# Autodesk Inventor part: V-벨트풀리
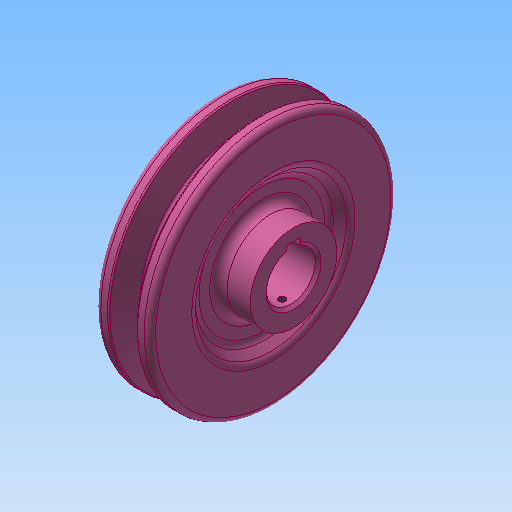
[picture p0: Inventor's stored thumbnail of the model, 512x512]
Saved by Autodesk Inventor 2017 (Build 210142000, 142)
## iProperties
Company: 한국ATC센터
Created: 2015-12
Part Number: V-벨트풀리
Document SubType Name: Modeling
Designer: mdu
Density: 7.25 g/cm^3
Mass: 596.066 g
Surface Area: 214.402 cm^2
Volume: 82.216 cm^3
Material: 주철
Appearance: 분홍색
Author: mdu
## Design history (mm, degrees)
sketch "스케치1"
  geometry: L1 (-13, 0)-(13, 0); L2 (-13, 0)-(-13, 15); L3 (-13, 15)-(-9, 15); L4 (-9, 15)-(-9, 23); L5 (-9, 23)-(-13, 27); L6 (-13, 27)-(-13, 42.7); L7 (-13, 42.7)-(-8.325, 42.7); L8 (-8.325, 42.7)-(-5.574, 33.7); L9 (-5.574, 33.7)-(-1.426, 33.7); L10 (-1.426, 33.7)-(1.325, 42.7); L11 (1.325, 42.7)-(6, 42.7); L12 (6, 42.7)-(6, 27); L13 (6, 27)-(2, 23); L14 (2, 23)-(2, 15); L15 (2, 15)-(13, 15); L16 (13, 15)-(13, 0); L17 (-7.5, 40)-(0.5, 40); 2 further points
  constraints: 34 end point, 6 parallel, 5 collinear, 5 equal length, 4 perpendicular, 2 point on line, 1 coincident, 1 horizontal, 1 midpoint
  dimensions: "d0" = 26 distance of L1.start L1.end; "d1" = 2.7 distance between parallel lines of L7 L17; "d2" = 6.3 distance between parallel lines of L9 L17; "d3" = 8 distance of L17.start L17.end; "d4" = 34 deg angle of L10 L8; "d5" = 19 distance between parallel lines of L12 L6; "d7" = 30 diameter of L15 L1; "d8" = 46 diameter of L13.end L1; "d9" = 54 diameter of L12.end L1; "d10" = 4 distance between parallel lines of L2 L4; "d11" = 80 diameter of L17 L1
revolve "회전1" sketch "스케치1" stored, may be unused: angle "d12" = 90 deg
sketch "스케치2"
  geometry: L1 (-2.5, 8.124)-(-2.5, 10.8); L2 (-2.5, 10.8)-(2.5, 10.8); L3 (2.5, 10.8)-(2.5, 8.124); A1 r 8.5 centre (0, 0) between (-2.5, 8.124) and (2.5, 8.124); 1 further point
  constraints: 6 end point, 2 parallel, 2 point on circle, 1 centre point, 1 coincident, 1 perpendicular, 1 vertical
  dimensions: "d13" = 17 diameter of A1; "d14" = 19.3 dimension on A1 L2; "d15" = 5 distance of L1.end L2.end
extrude "돌출1" cut sketch "스케치2" stored distance "d16" = 10; taper "d17" = 0 deg
node "작업 평면1"
sketch "스케치3"
  geometry: L1 (-5.5, 15)-(-5.5, -15) reference; L2 (20.5, 27)-(20.5, -27) reference; 3 further points
  constraints: 1 horizontal alignment, 1 midpoint
  dimensions: "d18" = 4 distance from line of point (-1.5, 0) L1; "d33" = 22 distance from line of point (-1.5, 0) L2 (derived)
hole "구멍1" sketch "스케치3" at (-1.5, 0) diameter "d19" = 2.459; stored, may be unused: countersink angle "d23" = 90 deg, drill point angle "d25" = 118 deg; dims "d20" = 6, "d21" = 4, "d22" = 2, "d24" = 8
fillet "모깎기1" dims "d26" = 2, "d27" = 0.5, "d28" = 1, "d29" = 3
chamfer "모따기1" distance "d30" = 1; stored, may be unused: second distance "d31" = 2, angle "d32" = 45 deg
sketch "스케치4" dims "d35" = 70
  geometry: C1 r 2 at (35, 0); 2 further points
  constraints: 2 horizontal alignment, 1 centre point, 1 coincident, 2 other
  dimensions: "d34" = 4 diameter of C1
extrude "돌출2" cut sketch "스케치4" distance "d36" = 1; taper "d37" = 0 deg
fillet "모깎기3" dims "d40" = 0.5
node "솔리드1"
